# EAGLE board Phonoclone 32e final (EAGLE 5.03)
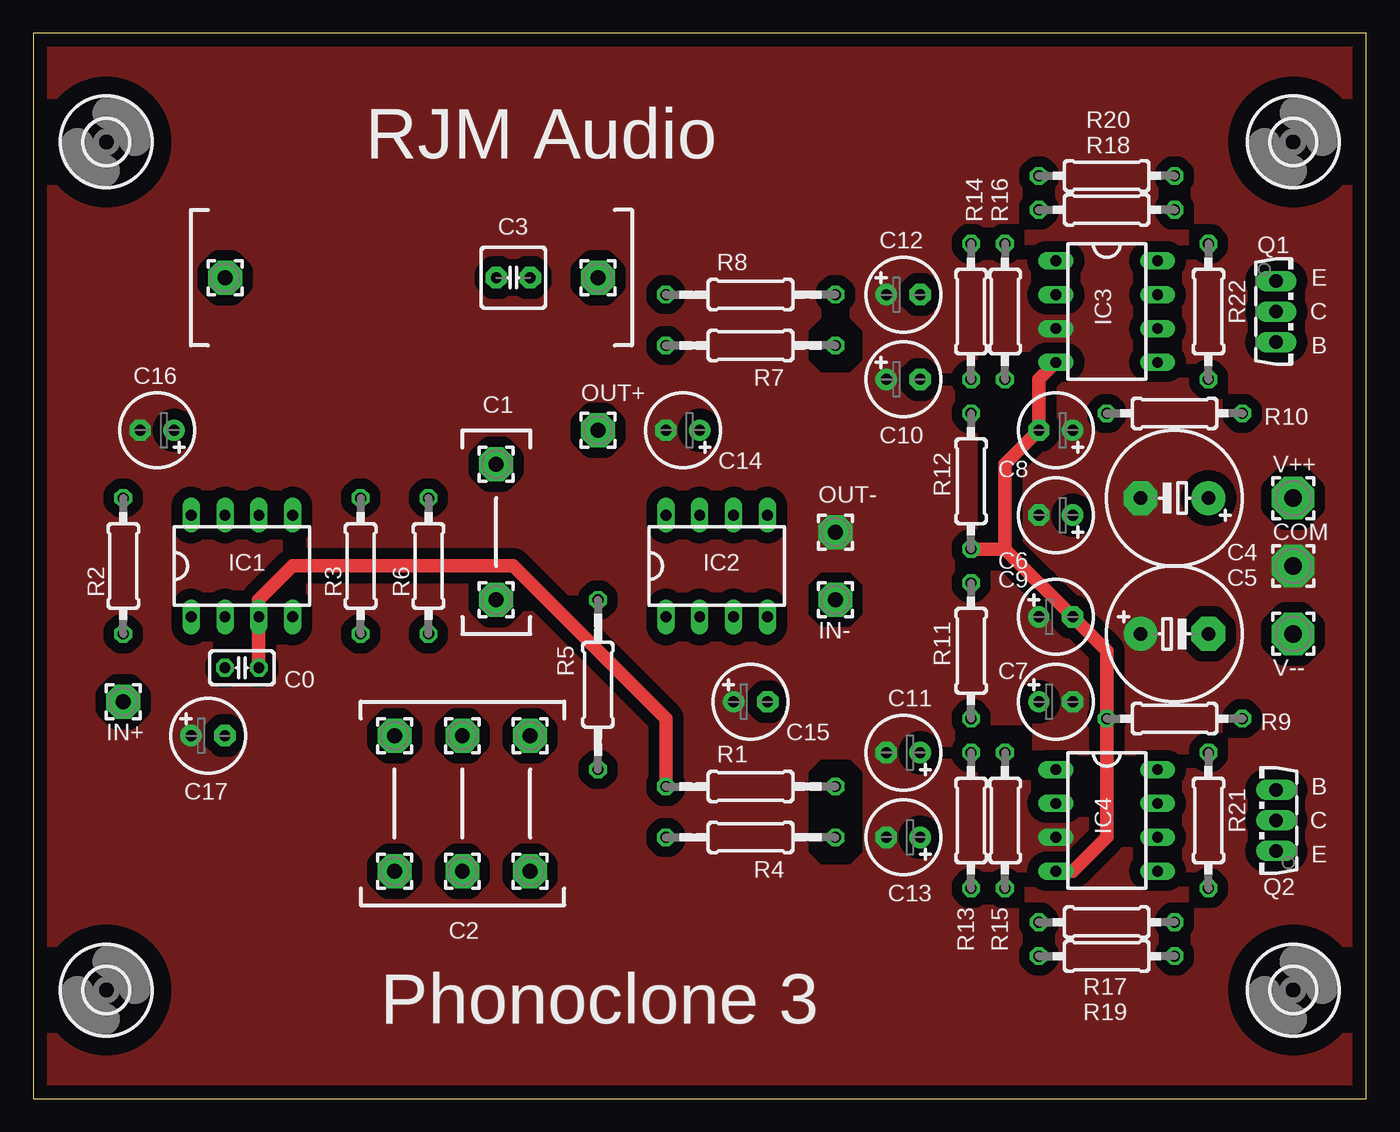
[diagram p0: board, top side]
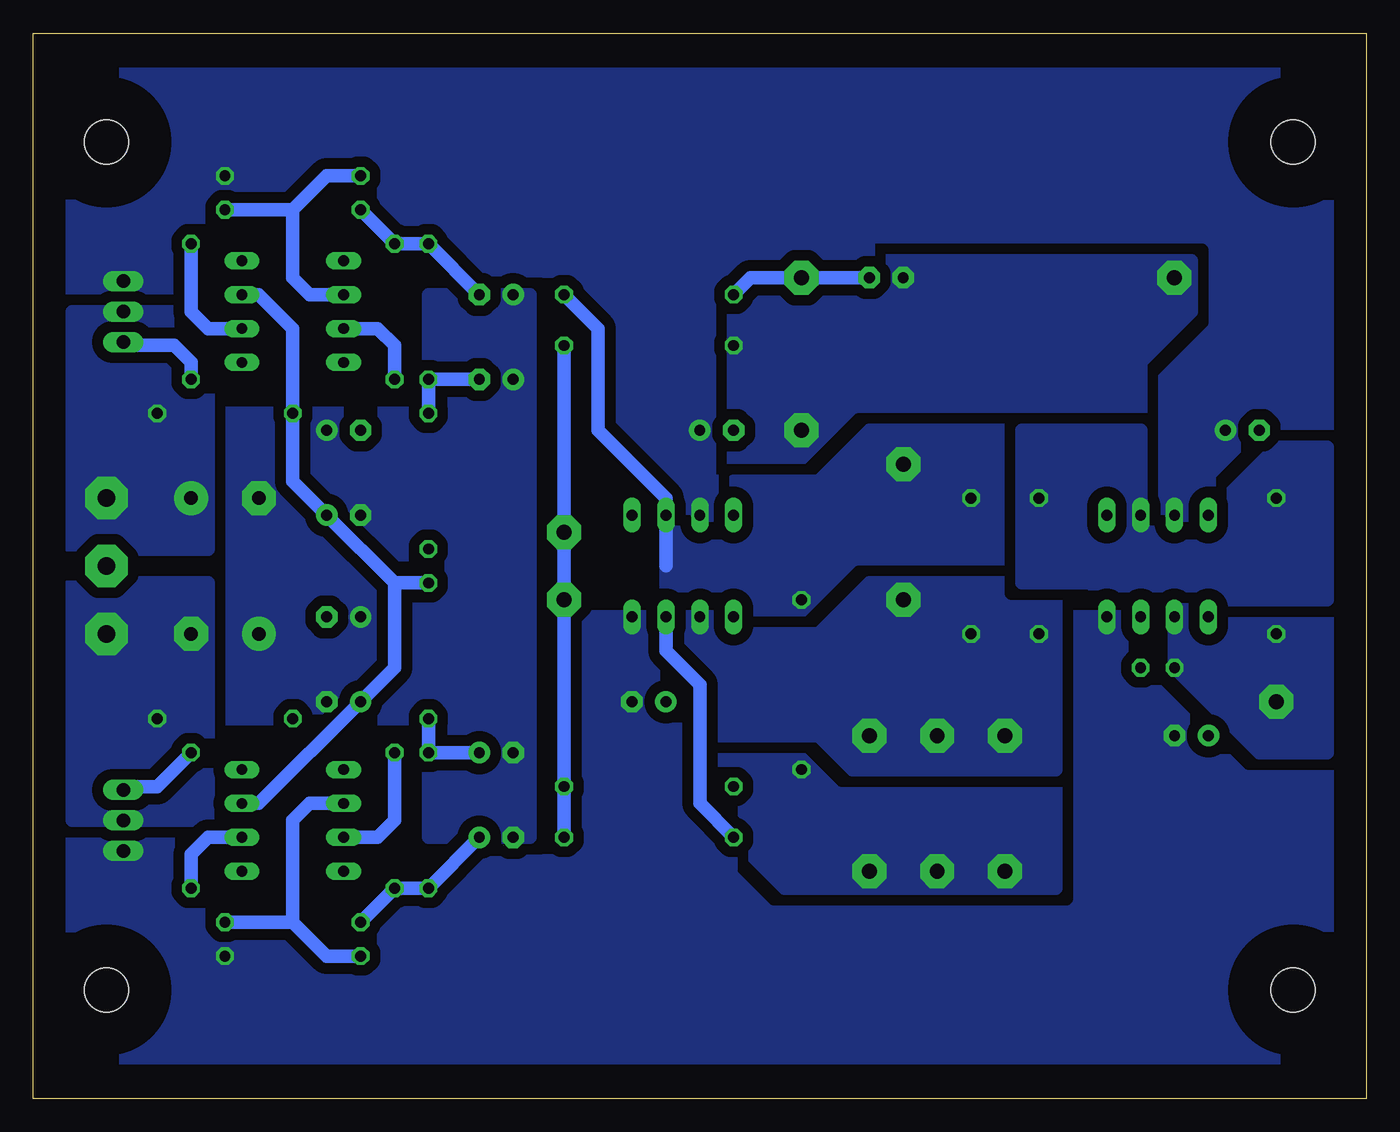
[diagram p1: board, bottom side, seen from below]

Size 99.82 x 79.76 mm. Coordinates in mm from the lower left corner, seen from the top.
Outline: 0,0 99.82,0 99.82,79.76 0,79.76 0,0
Copper layers (1*16): Top 0.035mm / dielectric 1.5mm / Bottom 0.035mm
Design rules "10mils": minimum track width 10mil, minimum drill 24mil, track to track 10mil, track to pad 10mil, pad to pad 10mil, via to via 10mil, smd to smd 10mil, copper to edge 40mil, drill to drill 10mil, minimum pad ring 10mil, minimum via ring 8mil, stop-mask expansion 0mil, vias tented up to drill 0mil, thermal gap 10mil

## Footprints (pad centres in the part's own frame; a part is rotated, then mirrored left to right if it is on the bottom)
C025-025X050 = drill 0.813 octagon: 1 -1.27,0; 2 1.27,0
2,54/1,1 = drill 1.118 pad 2.54 octagon: 1 0,0
C2.5-5 = drill 0.813 pad 1.6 octagon: 1 -1.27,0; 2 1.27,0
E5-10,5 = drill 1.016 pad 2.54 round: + -2.54,0 | drill 1.016 pad 2.54 octagon: - 2.54,0
E2,5-6 = drill 0.813 pad 1.6 round: + -1.27,0 | drill 0.813 pad 1.6 octagon: - 1.27,0
3,17/1,3 = drill 1.321 pad 3.175 octagon: 1 0,0
DIL08 = drill 0.813 long: 1 -3.81,-3.81; 2 -1.27,-3.81; 3 1.27,-3.81; 4 3.81,-3.81; 5 3.81,3.81; 6 1.27,3.81; 7 -1.27,3.81; 8 -3.81,3.81
TO126AV = drill 1.016 long: B 2.286,-1.27; C 0,-1.27; E -2.286,-1.27
0207/12 = drill 0.813 octagon: 1 -6.35,0; 2 6.35,0
0207/10 = drill 0.813 octagon: 1 -5.08,0; 2 5.08,0
3,3 = hole 3.3: 0,0

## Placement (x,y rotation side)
C0  [C025-025X050]  15.62,32.26 180 top
C1A  [2,54/1,1]  27.05,27.18 0 top
C3  2.2u  [C2.5-5]  35.94,61.47 180 top
C4  1000u  [E5-10,5]  85.47,44.96 180 top
C5  1000u  [E5-10,5]  85.47,34.8 0 top
C6  100u  [E2,5-6]  76.58,43.69 180 top
C7  100u  [E2,5-6]  76.58,29.72 0 top
C8  100u  [E2,5-6]  76.58,50.04 180 top
C9  100u  [E2,5-6]  76.58,36.07 0 top
C10  100u  [E2,5-6]  65.15,53.85 0 top
C11  100u  [E2,5-6]  65.15,25.91 180 top
C12  100u  [E2,5-6]  65.15,60.2 0 top
C13  100u  [E2,5-6]  65.15,19.56 180 top
C14  100u  [E2,5-6]  48.64,50.04 180 top
C15  100u  [E2,5-6]  53.72,29.72 0 top
C16  100u  [E2,5-6]  9.27,50.04 180 top
C17  100u  [E2,5-6]  13.08,27.18 0 top
COM  [3,17/1,3]  94.36,39.88 0 top
IC1  OP27Z  [DIL08]  15.62,39.88 0 top
IC2  OP27Z  [DIL08]  51.18,39.88 0 top
IC3  OP27Z  [DIL08]  80.39,58.93 270 top
IC4  OP27Z  [DIL08]  80.39,20.83 270 top
IN+  [2,54/1,1]  6.73,29.72 0 top
IN-  [2,54/1,1]  60.07,37.34 0 top
OUT+  [2,54/1,1]  42.29,50.04 0 top
OUT-  [2,54/1,1]  60.07,42.42 0 top
PAD2  [2,54/1,1]  32.13,27.18 0 top
PAD3  [2,54/1,1]  37.21,27.18 0 top
PAD4  [2,54/1,1]  34.67,37.34 0 top
PAD5  [2,54/1,1]  42.29,61.47 0 top
PAD6  [2,54/1,1]  14.35,61.47 0 top
PAD7  [2,54/1,1]  34.67,47.5 0 top
PAD8  [2,54/1,1]  27.05,17.02 0 top
PAD9  [2,54/1,1]  32.13,17.02 0 top
PAD10  [2,54/1,1]  37.21,17.02 0 top
Q1  BD135  [TO126AV]  94.36,58.93 270 top
Q2  BD136  [TO126AV]  91.82,20.83 90 top
R1  var.  [0207/12]  53.72,23.37 0 top
R2  var.  [0207/10]  6.73,39.88 90 top
R3  2k2  [0207/10]  24.51,39.88 270 top
R4  2k2  [0207/12]  53.72,19.56 0 top
R5  110k  [0207/12]  42.29,30.99 90 top
R6  768k  [0207/10]  29.59,39.88 90 top
R7  75k  [0207/12]  53.72,56.39 0 top
R8  47  [0207/12]  53.72,60.2 180 top
R9  220  [0207/10]  85.47,28.45 180 top
R10  220  [0207/10]  85.47,51.31 180 top
R11  30k  [0207/10]  70.23,33.53 270 top
R12  30k  [0207/10]  70.23,46.23 270 top
R13  30k  [0207/10]  70.23,20.83 270 top
R14  30k  [0207/10]  70.23,58.93 270 top
R15  2k2  [0207/10]  72.77,20.83 90 top
R16  2k2  [0207/10]  72.77,58.93 270 top
R17  2k2  [0207/10]  80.39,13.21 0 top
R18  2k2  [0207/10]  80.39,66.55 0 top
R19  75k  [0207/10]  80.39,10.67 0 top
R20  75k  [0207/10]  80.39,69.09 0 top
R21  47  [0207/10]  88.01,20.83 270 top
R22  47  [0207/10]  88.01,58.93 270 top
U$1  [3,3]  5.46,71.63 0 top
U$2  [3,3]  94.36,71.63 0 top
U$3  [3,3]  94.36,8.13 0 top
U$4  [3,3]  5.46,8.13 0 top
V++  [3,17/1,3]  94.36,44.96 0 top
V--  [3,17/1,3]  94.36,34.8 0 top

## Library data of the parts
C0 C4-C17 R1-R22 = rcl
C1A COM IN+ IN- OUT+ OUT- PAD2-PAD10 V++ V-- = wirepad
C3 = capacitor-wima
IC1-IC4 = linear
Q1 Q2 = transistor-power
U$1-U$4 = holes

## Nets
GND: C4.- C5.+ C6.- C7.- C8.+ C9.+ C10.+ C11.- C12.+ C13.- C14.- C15.+ C16.- C17.+ COM.1 IC3.3 IC4.3 IN-.1 OUT-.1 R1.2 R4.2 R7.2 R15.2 R16.2
IN: C0.2 IC1.2 IN+.1 R2.1
N$2: C3.1 PAD5.1 R8.2
N$4: C11.+ R11.2 R13.1
N$6: IC3.6 R22.1
N$7: Q1.B R22.2
N$8: C0.1 IC1.3 R1.1
N$9: IC4.2 R17.2 R19.1
N$10: Q2.B R21.1
N$11: IC4.6 R21.2
N$13: IC3.2 R18.2 R20.1
N$14: C10.- R12.1 R14.2
OUT: IC1.6 R2.2 R3.1
OUT1: IC2.6 PAD7.1 R5.2 R6.2 R8.1
OUT2: C3.2 OUT+.1 PAD6.1 R7.1
P2+: IC2.3 R4.1
RIAA1: C1A.1 IC2.2 PAD2.1 PAD3.1 PAD4.1 R3.2 R6.1
RIAA2: PAD8.1 PAD9.1 PAD10.1 R5.1
V+: C6.+ C7.+ IC3.7 IC4.7 R10.2 R11.1
V++: C4.+ Q1.C R10.1 V++.1
V+REG: C14.+ C16.+ IC1.7 IC2.7 Q1.E R20.2
V-: C8.- C9.- IC3.4 IC4.4 R9.2 R12.2
V--: C5.- Q2.C R9.1 V--.1
V-REG: C15.- C17.- IC1.4 IC2.4 Q2.E R19.2
VREF+: C13.+ R13.2 R15.1 R17.1
VREF-: C12.- R14.1 R16.1 R18.1

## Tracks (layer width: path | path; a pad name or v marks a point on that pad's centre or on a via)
GND
  Bottom 1.016: R7.2 OUT-.1 IN-.1 R1.2 R4.2 | R16.2 72.77,56.39 74.04,57.66 IC3.3 | R15.2 72.77,20.83 74.04,19.56 IC4.3
  pour Top (isolate 0.813, no thermals): 0.38,0.51 0.38,79.25 57.53,79.25 57.53,0.51
  pour Top (isolate 0.813, no thermals): 57.53,79.25 70.23,79.25 70.23,0.51 57.53,0.51 57.53,18.29 58.8,17.02 61.34,17.02 62.61,18.29 62.61,24.64 61.34,25.91 58.8,25.91 57.53,24.64 57.53,36.07 58.8,34.8 61.34,34.8 62.61,36.07 62.61,38.61 61.34,39.88 58.8,39.88 57.53,38.61 57.53,55.12 58.8,53.85 61.34,53.85 62.61,55.12 62.61,57.66 61.34,58.93 58.8,58.93 57.53,57.66
  pour Top (isolate 0.813, no thermals): 70.23,79.25 99.44,79.25 99.44,0.51 70.23,0.51 70.23,23.37 75.31,23.37 75.31,28.45 70.23,28.45 70.23,51.31 75.31,51.31 75.31,56.39 70.23,56.39
  pour Bottom (isolate 0.813, rank 5, no thermals): 62.61,51.31 62.61,28.45 88.01,28.45 88.01,51.31
  pour Bottom (isolate 0.813, rank 5, no thermals): 62.61,28.45 70.23,28.45 70.23,19.56 62.61,19.56
  pour Bottom (isolate 0.813, rank 5, no thermals): 62.61,51.31 62.61,60.2 70.23,60.2 70.23,51.31
IN
  pour Bottom (isolate 0.813, rank 4, no thermals): 2.92,38.61 14.35,38.61 14.35,32.26 8,25.91 2.92,25.91
N$2
  Bottom 1.016: R8.2 46.1,61.47 PAD5.1 C3.1
N$4
  Bottom 1.016: C11.+ R13.1 R11.2
N$6
  Bottom 1.016: IC3.6 86.74,57.66 88.01,58.93 R22.1
N$7
  Bottom 1.016: R22.2 88.01,55.12 89.28,56.39 92.84,56.39 Q1.B
N$8
  Top 1.016: R1.1 47.37,28.45 35.94,39.88 19.43,39.88 16.89,37.34 IC1.3 C0.1
N$9
  Bottom 1.016: IC4.2 79.12,22.1 80.39,20.83 80.39,13.21 | R19.1 77.85,10.67 80.39,13.21 | 80.39,13.21 R17.2
N$10
  Bottom 1.016: R21.1 90.55,23.37 92.84,23.37 Q2.B
N$11
  Bottom 1.016: IC4.6 86.74,19.56 88.01,18.29 R21.2
N$13
  Bottom 1.016: IC3.2 79.12,60.2 80.39,61.47 80.39,66.55 | 80.39,66.55 R18.2 | 80.39,66.55 77.85,69.09 R20.1
N$14
  Bottom 1.016: C10.- R14.2 R12.1
OUT
  pour Bottom (isolate 0.813, rank 2, no thermals): 2.92,48.77 6.73,48.77 13.08,42.42 16.89,42.42 16.89,50.04 25.78,50.04 25.78,38.61 20.7,38.61 19.43,37.34 2.92,37.34
OUT1
  Bottom 1.016: 52.45,39.88 IC2.6 52.45,44.96 57.53,50.04 57.53,57.66 R8.1
  pour Bottom (isolate 0.813, rank 4, no thermals): 25.78,34.8 52.45,34.8 52.45,42.42 47.37,42.42 47.37,46.23 41.02,46.23 37.21,50.04 25.78,50.04
OUT2
  pour Bottom (isolate 0.813, rank 5, no thermals): 13.08,62.74 13.08,58.93 16.89,55.12 16.89,46.23 47.37,46.23 47.37,60.2 38.48,60.2 35.94,62.74
P2+
  Bottom 1.016: R4.1 49.91,22.1 49.91,30.99 52.45,33.53 IC2.3
RIAA1
  pour Bottom (isolate 0.813, rank 3, no thermals): 23.24,38.61 23.24,24.64 38.48,24.64 41.02,27.18 49.91,27.18 49.91,30.99 51.18,32.26 51.18,36.07 48.64,36.07 48.64,34.8 41.02,34.8 37.21,38.61
RIAA2
  pour Bottom (isolate 0.813, rank 5, no thermals): 23.24,28.45 49.91,28.45 49.91,22.1 43.56,15.75 23.24,15.75
V+
  Bottom 1.016: IC3.7 82.93,60.2 80.39,57.66 R10.2 80.39,46.23 C6.+ 72.77,38.61 | IC4.7 82.93,22.1 C7.+ 72.77,32.26 72.77,38.61 | 72.77,38.61 R11.1
V++
  pour Bottom (isolate 0.813, no thermals): 86.74,41.15 96.9,41.15 96.9,58.93 86.74,58.93
V+REG
  pour Bottom (isolate 0.813, rank 6, no thermals): 2.92,43.69 2.92,76.71 96.9,76.71 96.9,43.69
V-
  Top 1.016: IC3.4 75.31,53.85 C8.- 72.77,47.5 72.77,41.15 | IC4.4 77.85,17.02 80.39,19.56 R9.2 80.39,30.99 80.39,33.53 C9.- 72.77,41.15 | 72.77,41.15 R12.2
V--
  pour Bottom (isolate 0.813, no thermals): 86.74,38.61 96.9,38.61 96.9,20.83 86.74,20.83
V-REG
  pour Bottom (isolate 0.813, rank 6, no thermals): 2.92,3.05 2.92,36.07 96.9,36.07 96.9,3.05
VREF+
  Bottom 1.016: R15.1 R17.1 R15.1 | C13.+ R13.2 R15.1
VREF-
  Bottom 1.016: R18.1 R16.1 R14.1 C12.-

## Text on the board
tPlace: RJM Audio | Phonoclone 3
tNames: E | C | B | C1 | B | C | E | C2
